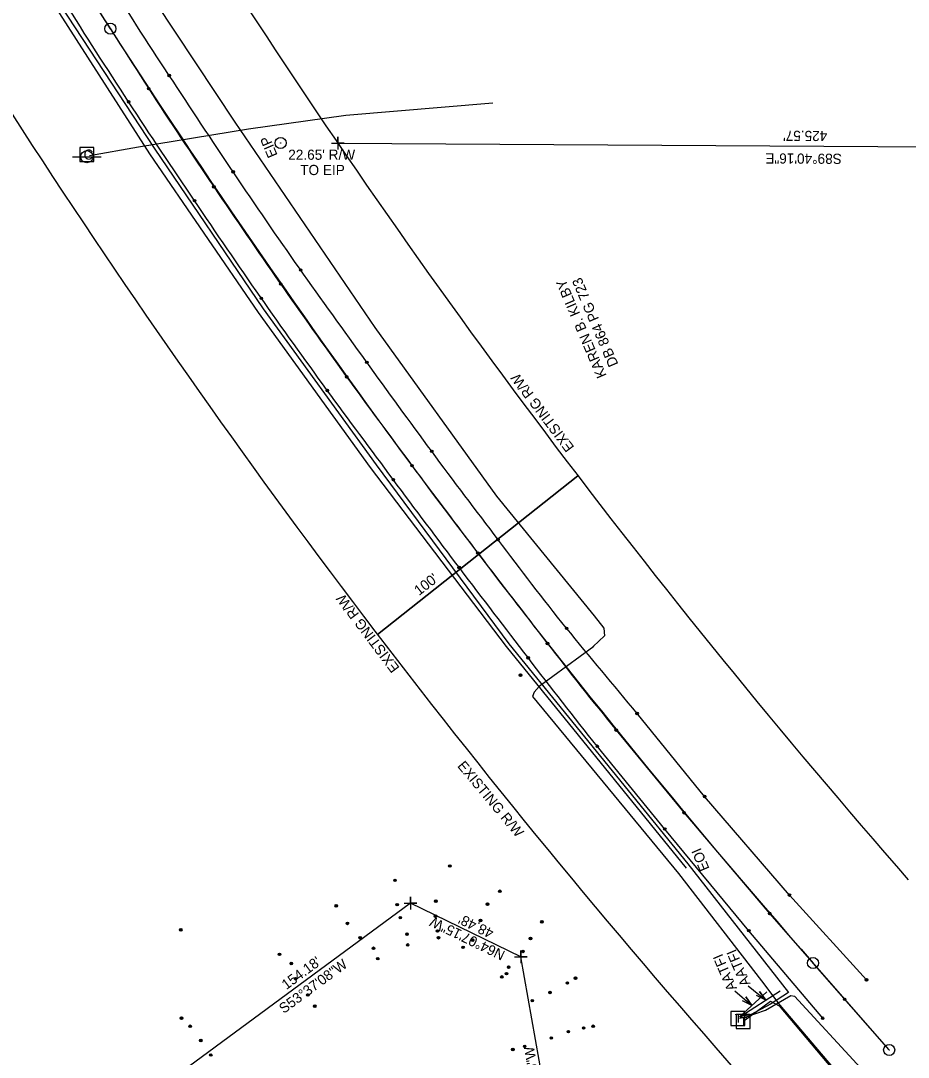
# Model space of a CAD drawing. Extents: x 1550153 to 1552579, y 809637 to 812160.
# Drawn here: x 1552025.7 to 1552376.2, y 809876 to 810285.6 of the extents above; entities that cross this region are included whole.
import ezdxf

# ---------------------------------------------------------------- set-up
doc = ezdxf.new("R2010")
doc.units = 0
for name, color, linetype in [('Default', 7, 'Continuous'), ('E_NCDOT_Horizontal_Alignment', 7, 'Continuous'), ('E_NCDOT_Horizontal_Alignment_Curve', 7, 'Continuous'), ('E_NCDOT_Horizontal_Alignment_Tick_Label', 7, 'Continuous'), ('Exist DTM Crownline', 7, 'Continuous'), ('Exist Other Culture Area Outline Text', 7, 'Continuous'), ('Exist Property Corner CELL', 7, 'Continuous'), ('Exist Property Iron Pin CELL', 7, 'Continuous'), ('Exist Property Iron Pin Text', 7, 'Continuous'), ('Exist Property Line', 7, 'Continuous'), ('Exist Property Line Text', 7, 'Continuous'), ('Exist Property Text', 7, 'Continuous'), ('Exist Right of Way Line', 7, 'Continuous'), ('Exist Right of Way Line Leader', 7, 'Continuous'), ('Exist Right of Way Line Text', 7, 'Continuous'), ('Exist Roads EOP', 7, 'Continuous'), ('Exist Utilities Other Text', 7, 'Continuous'), ('Exist Utilities Other Unknown UG SUE LOS B', 7, 'Continuous'), ('Exist Utilities Telephone Pedestal CELL', 7, 'Continuous'), ('Exist Utilities Telephone Pole CELL', 7, 'Continuous'), ('Exist Utilities Telephone Text', 7, 'Continuous'), ('Exist Utilities Telephone UG Cable SUE LOS B', 7, 'Continuous'), ('Exist Utilities Telephone UG FO SUE LOS B', 7, 'Continuous'), ('Exist Utilities TV Pedestal CELL', 7, 'Continuous'), ('Exist Utilities TV UG Cable SUE LOS B', 7, 'Continuous')]:
    doc.layers.add(name, color=color, linetype=linetype)

# ---------------------------------------------------------------- blocks, each defined once
blk = doc.blocks.new('SurveyPointCell')
at = {"layer": 'Default'}
for p, q in [((-0.5, 0), (0.5, 0)), ((0, -0.5), (0, 0.5))]:
    blk.add_line(p, q, dxfattribs=at)
blk.add_circle((0, 0), 0.5, dxfattribs=at)

msp = doc.modelspace()

# ---------------------------------------------------------------- linework, layer by layer
at = {"layer": 'Default'}
msp.add_arc((1554670.98, 811955.32), 3100, 212.65834, 221.20382, dxfattribs=at)
msp.add_arc((1554670.98, 811955.32), 3100, 212.65834, 221.20382, dxfattribs=at)
msp.add_arc((1554670.98, 811955.32), 3100, 212.65834, 221.20382, dxfattribs=at)
at = {"layer": 'E_NCDOT_Horizontal_Alignment'}
for p, q in [((1552061.08, 810282.48), (1552050.68, 810298.74)), ((1552368.71, 809878.88), (1552338.63, 809913.23))]:
    msp.add_line(p, q, dxfattribs=at)
for centre, radius in [((1552061.08, 810282.48), 2.2), ((1552061.08, 810282.48), 0.0707), ((1552338.63, 809913.23), 2.2), ((1552338.63, 809913.23), 0.0707), ((1552368.71, 809878.88), 2.2), ((1552368.71, 809878.88), 0.0707)]:
    msp.add_circle(centre, radius, dxfattribs=at)
at = {"layer": 'E_NCDOT_Horizontal_Alignment_Curve'}
msp.add_arc((1554670.98, 811955.32), 3100, 212.65834, 221.20382, dxfattribs=at)
msp.add_arc((1554670.98, 811955.32), 3100, 212.65834, 221.20382, dxfattribs=at)
at = {"layer": 'E_NCDOT_Horizontal_Alignment_Tick_Label'}
msp.add_arc((1554670.98, 811955.32), 3100, 212.65834, 221.20382, dxfattribs=at)
at = {"layer": 'Exist DTM Crownline'}
for p, q in [((1552260.85, 810005.29), (1552287.67, 809972.63)), ((1552260.85, 810005.29), (1552287.67, 809972.63)), ((1552287.67, 809972.63), (1552321.49, 809932.79)), ((1552287.67, 809972.63), (1552321.49, 809932.79)), ((1552321.49, 809932.79), (1552351.14, 809898.88)), ((1552321.49, 809932.79), (1552351.14, 809898.88))]:
    msp.add_line(p, q, dxfattribs=at)
msp.add_open_spline([(1551879.82, 810614.22), (1551884.05, 810605.39), (1551895.17, 810581.82), (1551913.83, 810543.92), (1551935.88, 810500.73), (1551958.31, 810458.41), (1551980.95, 810417.48), (1552003.45, 810377.54), (1552026.55, 810337.94), (1552050.88, 810298.4), (1552075.94, 810258.8), (1552101.84, 810219.91), (1552127.91, 810181.93), (1552154.01, 810145.21), (1552180.08, 810109.84), (1552206.53, 810074.71), (1552233.39, 810039.85), (1552251.62, 810016.53), (1552260.85, 810005.29)], degree=3, dxfattribs=at)
msp.add_open_spline([(1551879.82, 810614.22), (1551884.05, 810605.39), (1551895.17, 810581.82), (1551913.83, 810543.92), (1551935.88, 810500.73), (1551958.31, 810458.41), (1551980.95, 810417.48), (1552003.45, 810377.54), (1552026.55, 810337.94), (1552050.88, 810298.4), (1552075.94, 810258.8), (1552101.84, 810219.91), (1552127.91, 810181.93), (1552154.01, 810145.21), (1552180.08, 810109.84), (1552206.53, 810074.71), (1552233.39, 810039.85), (1552251.62, 810016.53), (1552260.85, 810005.29)], degree=3, dxfattribs=at)
at = {"layer": 'Exist Other Culture Area Outline Text'}
msp.add_line((1552368.71, 809878.88), (1552351.02, 809899.07), dxfattribs=at)
at = {"layer": 'Exist Property Corner CELL'}
for p, q in [((1552150.95, 810237.19), (1552150.95, 810237.19)), ((1552179.62, 809936.85), (1552179.62, 809936.85)), ((1552223.24, 809915.69), (1552223.24, 809915.69))]:
    msp.add_line(p, q, dxfattribs=at)
for points in [[(1552148.45, 810237.19), (1552153.45, 810237.19), (1552150.95, 810237.19), (1552150.95, 810239.69), (1552150.95, 810234.69)], [(1552177.12, 809936.85), (1552182.12, 809936.85), (1552179.62, 809936.85), (1552179.62, 809939.35), (1552179.62, 809934.35)], [(1552220.74, 809915.69), (1552225.74, 809915.69), (1552223.24, 809915.69), (1552223.24, 809918.19), (1552223.24, 809913.19)]]:
    msp.add_lwpolyline(points, dxfattribs=at)
at = {"layer": 'Exist Property Iron Pin CELL'}
for radius in [2.2, 2.2, 0.0707, 0.0707]:
    msp.add_circle((1552128.3, 810237.32), radius, dxfattribs=at)
at = {"layer": 'Exist Property Line'}
for p, q in [((1552150.95, 810237.19), (1552576.51, 810234.75)), ((1552179.62, 809936.85), (1552055.49, 809845.39)), ((1552223.24, 809915.69), (1552179.62, 809936.85)), ((1552240.21, 809820.15), (1552223.24, 809915.69))]:
    msp.add_line(p, q, dxfattribs=at)
at = {"layer": 'Exist Right of Way Line'}
msp.add_line((1552300.27, 809879.66), (1552330.35, 809845.3), dxfattribs=at)
for centre, radius, start in [((1554670.98, 811955.32), 3050, 212.65885), ((1554670.24, 811954.69), 3150, 212.65834)]:
    msp.add_arc(centre, radius, start, 221.20382, dxfattribs=at)
at = {"layer": 'Exist Right of Way Line Leader'}
for p, q in [((1552166.59, 810043.11), (1552245.77, 810105.76)), ((1552245.77, 810105.76), (1552166.59, 810043.11))]:
    msp.add_line(p, q, dxfattribs=at)
at = {"layer": 'Exist Roads EOP'}
for p, q in [((1552295.82, 809979.06), (1552269.13, 810011.86)), ((1552295.82, 809979.06), (1552269.13, 810011.86)), ((1552280.06, 809966.19), (1552253.42, 809998.9)), ((1552280.06, 809966.19), (1552253.42, 809998.9)), ((1552329.3, 809940.08), (1552295.82, 809979.06)), ((1552329.3, 809940.08), (1552295.82, 809979.06)), ((1552313.28, 809926.01), (1552280.06, 809966.19)), ((1552313.28, 809926.01), (1552280.06, 809966.19)), ((1552359.73, 809906.61), (1552329.3, 809940.08)), ((1552359.73, 809906.61), (1552329.3, 809940.08)), ((1552342.44, 809891.42), (1552313.28, 809926.01)), ((1552342.44, 809891.42), (1552313.28, 809926.01))]:
    msp.add_line(p, q, dxfattribs=at)
for points in [[(1552269.13, 810011.86), (1552259.93, 810023.16), (1552240.78, 810045.4), (1552214.35, 810080.42), (1552187.88, 810115.33), (1552162.14, 810151.01), (1552135.65, 810187.58), (1552109.73, 810225.45), (1552084.16, 810264.07), (1552058.92, 810303.06), (1552035.07, 810342.61), (1552011.65, 810381.94), (1551989.05, 810421.66), (1551966.76, 810462.54), (1551944.71, 810504.82), (1551922.39, 810547.43), (1551904.23, 810585.99), (1551891.95, 810609.53), (1551888.02, 810619.12)], [(1552269.13, 810011.86), (1552259.93, 810023.16), (1552240.78, 810045.4), (1552214.35, 810080.42), (1552187.88, 810115.33), (1552162.14, 810151.01), (1552135.65, 810187.58), (1552109.73, 810225.45), (1552084.16, 810264.07), (1552058.92, 810303.06), (1552035.07, 810342.61), (1552011.65, 810381.94), (1551989.05, 810421.66), (1551966.76, 810462.54), (1551944.71, 810504.82), (1551922.39, 810547.43), (1551904.23, 810585.99), (1551891.95, 810609.53), (1551888.02, 810619.12)], [(1552253.42, 809998.9), (1552244.08, 810010.36), (1552226.02, 810034.01), (1552199.09, 810069.05), (1552172.75, 810104.35), (1552146.51, 810139.68), (1552120.18, 810176.35), (1552094.25, 810214.54), (1552068.09, 810253.47), (1552042.85, 810293.18), (1552018.16, 810332.74), (1551995.33, 810372.57), (1551972.36, 810412.53), (1551950.07, 810453.8), (1551927.46, 810496.24), (1551905.63, 810539.48), (1551886.95, 810576.34), (1551876.35, 810599.18), (1551872.14, 810607.04)], [(1552253.42, 809998.9), (1552244.08, 810010.36), (1552226.02, 810034.01), (1552199.09, 810069.05), (1552172.75, 810104.35), (1552146.51, 810139.68), (1552120.18, 810176.35), (1552094.25, 810214.54), (1552068.09, 810253.47), (1552042.85, 810293.18), (1552018.16, 810332.74), (1551995.33, 810372.57), (1551972.36, 810412.53), (1551950.07, 810453.8), (1551927.46, 810496.24), (1551905.63, 810539.48), (1551886.95, 810576.34), (1551876.35, 810599.18), (1551872.14, 810607.04)]]:
    msp.add_open_spline(points, degree=3, dxfattribs=at)
at = {"layer": 'Exist Utilities Other Unknown UG SUE LOS B'}
msp.add_lwpolyline([(1551998.29, 810358.65), (1552027.49, 810309.53), (1552076.51, 810232.97), (1552119.42, 810170.33), (1552163.65, 810109.03), (1552217.37, 810038.38), (1552288.47, 809950.78)], dxfattribs=at)
at = {"layer": 'Exist Utilities Telephone Pedestal CELL'}
for p, q in [((1552308.86, 809891.37), (1552308.86, 809891.37)), ((1552310.97, 809890.17), (1552310.97, 809890.17))]:
    msp.add_line(p, q, dxfattribs=at)
for points in [[(1552306.13, 809888.54), (1552311.73, 809888.54), (1552311.73, 809894.14), (1552306.13, 809894.14), (1552306.13, 809888.54)], [(1552308.24, 809887.34), (1552313.84, 809887.34), (1552313.84, 809892.93), (1552308.24, 809892.93), (1552308.24, 809887.34)]]:
    msp.add_lwpolyline(points, dxfattribs=at)
at = {"layer": 'Exist Utilities Telephone Pole CELL'}
for p, q in [((1552046.12, 810231.89), (1552057.46, 810231.89)), ((1552051.8, 810231.89), (1552051.8, 810231.89))]:
    msp.add_line(p, q, dxfattribs=at)
msp.add_circle((1552051.8, 810231.89), 2.41, dxfattribs=at)
at = {"layer": 'Exist Utilities Telephone Text'}
for points in [[(1552313.06, 809904.27), (1552320, 809898.6), (1552317.53, 809901.92), (1552320, 809898.6), (1552316.25, 809900.36)], [(1552307.68, 809902.3), (1552314.5, 809896.48), (1552312.1, 809899.85), (1552314.5, 809896.48), (1552310.79, 809898.32)]]:
    msp.add_lwpolyline(points, dxfattribs=at)
at = {"layer": 'Exist Utilities Telephone UG Cable SUE LOS B'}
for points in [[(1551973.26, 810338.34), (1551996.17, 810347.86), (1551999.41, 810348.48), (1552003.26, 810346.04), (1552024.7, 810309.34), (1552030.08, 810308.97), (1552078.4, 810235.23), (1552121.38, 810171.79), (1552166.12, 810110.11), (1552218.44, 810039.34), (1552289.22, 809952.46), (1552328.94, 809901.56), (1552321.82, 809896.99), (1552314.14, 809892.89), (1552309.87, 809891.97)], [(1552309.55, 809891.47), (1552312.19, 809891.91), (1552319.91, 809894.61), (1552329.89, 809900.42), (1552331.29, 809900.19), (1552357.54, 809871.63), (1552412.1, 809813.52), (1552394.77, 809791.06), (1552373.8, 809767.63)], [(1552309.62, 809892), (1552320.35, 809901.83)], [(1552309.74, 809892), (1552325.61, 809902.19)]]:
    msp.add_lwpolyline(points, dxfattribs=at)
at = {"layer": 'Exist Utilities Telephone UG FO SUE LOS B'}
for points in [[(1552044.44, 810374.04), (1552034.64, 810367.89), (1552033.1, 810366.21), (1552033.06, 810365.23), (1552055.35, 810328.54), (1552110.28, 810245.54), (1552165.47, 810164.33), (1552213.57, 810097.71), (1552252.14, 810050.46), (1552256.04, 810045.54), (1552256.3, 810042.48), (1552251.81, 810038.38)], [(1552252.06, 810038.28), (1552230.41, 810022.46), (1552228.43, 810020.33), (1552227.78, 810018.51), (1552285.44, 809948.57), (1552318.22, 809906.19), (1552325.57, 809896.61), (1552350.79, 809866.81), (1552393.46, 809818.55), (1552396.72, 809805.6), (1552391.99, 809793.83), (1552373.15, 809768.18)], [(1552311.27, 809890.39), (1552321.89, 809898.14), (1552325.31, 809896.34), (1552350.52, 809866.22), (1552392.74, 809818.07), (1552396.32, 809805.59), (1552391.17, 809793.53), (1552372.89, 809768.53)]]:
    msp.add_lwpolyline(points, dxfattribs=at)
at = {"layer": 'Exist Utilities TV Pedestal CELL'}
msp.add_line((1552051.77, 810232.73), (1552051.77, 810232.73), dxfattribs=at)
msp.add_lwpolyline([(1552049, 810229.96), (1552054.55, 810229.96), (1552054.55, 810235.51), (1552049, 810235.51), (1552049, 810229.96)], dxfattribs=at)
at = {"layer": 'Exist Utilities TV UG Cable SUE LOS B'}
msp.add_lwpolyline([(1552052.75, 810232.34), (1552072.2, 810235.77), (1552115.56, 810242.96), (1552154.04, 810248.3), (1552212.2, 810253.17)], dxfattribs=at)

# ---------------------------------------------------------------- block references
at = {"layer": 'Default'}
for p in [(1552084.32, 810263.97), (1552084.32, 810263.97), (1552076.17, 810258.78), (1552076.17, 810258.78), (1552068.28, 810253.55), (1552068.28, 810253.55), (1552109.57, 810225.89), (1552109.57, 810225.89), (1552101.92, 810219.98), (1552101.92, 810219.98), (1552094.32, 810214.5), (1552094.32, 810214.5), (1552136.23, 810187.11), (1552136.23, 810187.11), (1552128.32, 810181.56), (1552128.32, 810181.56), (1552120.71, 810175.94), (1552120.71, 810175.94), (1552162.39, 810150.64), (1552162.39, 810150.64), (1552154.39, 810144.9), (1552154.39, 810144.9), (1552146.79, 810139.5), (1552146.79, 810139.5), (1552188.02, 810115.43), (1552188.02, 810115.43), (1552180.2, 810109.81), (1552180.2, 810109.81), (1552172.86, 810104.22), (1552172.86, 810104.22), (1552214.18, 810080.63), (1552214.18, 810080.63), (1552206.22, 810075.25), (1552206.22, 810075.25), (1552198.86, 810069.53), (1552198.86, 810069.53), (1552241.29, 810045.52), (1552241.29, 810045.52), (1552233.73, 810039.5), (1552233.73, 810039.5), (1552226.12, 810033.84), (1552226.12, 810033.84), (1552223.06, 810026.98), (1552223.06, 810026.98), (1552269.13, 810011.86), (1552269.13, 810011.86), (1552260.85, 810005.29), (1552260.85, 810005.29), (1552253.42, 809998.9), (1552253.42, 809998.9), (1552295.82, 809979.06), (1552295.82, 809979.06), (1552287.67, 809972.63), (1552287.67, 809972.63), (1552280.06, 809966.19), (1552280.06, 809966.19), (1552195.17, 809951.6), (1552195.17, 809951.6), (1552173.48, 809945.94), (1552173.48, 809945.94), (1552214.92, 809941.61), (1552214.92, 809941.61), (1552329.3, 809940.08), (1552329.3, 809940.08), (1552150.28, 809935.83), (1552150.28, 809935.83), (1552174.36, 809936.3), (1552174.36, 809936.3), (1552189.61, 809937.68), (1552189.61, 809937.68), (1552210.02, 809936.48), (1552210.02, 809936.48), (1552175.6, 809931.14), (1552175.6, 809931.14), (1552189.5, 809931.74), (1552189.5, 809931.74), (1552321.49, 809932.79), (1552321.49, 809932.79), (1552154.7, 809928.89), (1552154.7, 809928.89), (1552207.25, 809930.02), (1552207.25, 809930.02), (1552231.53, 809929.5), (1552231.53, 809929.5), (1552088.86, 809926.35), (1552088.86, 809926.35), (1552159.72, 809923.22), (1552159.72, 809923.22), (1552178.25, 809924.63), (1552178.25, 809924.63), (1552190.26, 809925.9), (1552190.26, 809925.9), (1552190.66, 809923.22), (1552190.66, 809923.22), (1552227.04, 809922.95), (1552227.04, 809922.95), (1552313.28, 809926.01), (1552313.28, 809926.01), (1552165.01, 809919.08), (1552165.01, 809919.08), (1552178.52, 809920.39), (1552178.52, 809920.39), (1552200.39, 809919.42), (1552200.39, 809919.42), (1552204.19, 809922.29), (1552204.19, 809922.29), (1552127.85, 809916.66), (1552127.85, 809916.66), (1552166.68, 809914.97), (1552166.68, 809914.97), (1552224.06, 809917.82), (1552224.06, 809917.82), (1552132.52, 809913.06), (1552132.52, 809913.06), (1552218.37, 809911.62), (1552218.37, 809911.62), (1552134.22, 809907.02), (1552134.22, 809907.02), (1552215.7, 809907.75), (1552215.7, 809907.75), (1552217.52, 809909.01), (1552217.52, 809909.01), (1552244.8, 809907.27), (1552244.8, 809907.27), (1552359.73, 809906.61), (1552359.73, 809906.61), (1552241.58, 809905.36), (1552241.58, 809905.36), (1552139.07, 809900.6), (1552139.07, 809900.6), (1552227.74, 809898.36), (1552227.74, 809898.36), (1552234.74, 809901.57), (1552234.74, 809901.57), (1552351.14, 809898.88), (1552351.14, 809898.88), (1552141.79, 809896.18), (1552141.79, 809896.18), (1552089.16, 809891.44), (1552089.16, 809891.44), (1552342.44, 809891.42), (1552342.44, 809891.42), (1552092.58, 809888.26), (1552092.58, 809888.26), (1552241.98, 809886.09), (1552241.98, 809886.09), (1552248, 809887.58), (1552248, 809887.58), (1552251.76, 809888.26), (1552251.76, 809888.26), (1552096.76, 809882.61), (1552096.76, 809882.61), (1552235.23, 809883.62), (1552235.23, 809883.62), (1552220.03, 809879.07), (1552220.03, 809879.07), (1552224.73, 809880.33), (1552224.73, 809880.33), (1552100.71, 809876.89), (1552100.71, 809876.89)]:
    msp.add_blockref('SurveyPointCell', p, dxfattribs=at)

# ---------------------------------------------------------------- texts
at = {"layer": 'Exist Property Iron Pin Text'}
msp.add_text('EIP', height=4.02, rotation=113.1736, dxfattribs=at).set_placement((1552127.19, 810232.52))
at = {"layer": 'Exist Property Line Text'}
for s, rotation, p in [("425.57'", 179.6712, (1552344.27, 810242.07)), ('S89°40\'16"E', 179.6712, (1552350, 810233.05)), ("48.48'", 154.1208, (1552212.89, 809926.37)), ('N64°07\'15"W', 154.1208, (1552217.32, 809917.74)), ('S53°37\'08"W', 36.3811, (1552129.56, 809893.09)), ("154.18'", 36.3811, (1552130.58, 809902.52)), ('N10°04\'26"W', 100.0739, (1552233.93, 809849.02))]:
    msp.add_text(s, height=4.02, rotation=rotation, dxfattribs=at).set_placement(p)
for s, p in [("22.65' R/W", (1552131.32, 810230.66)), ('TO EIP', (1552136.05, 810224.63))]:
    msp.add_text(s, height=4.02, dxfattribs=at).set_placement(p)
at = {"layer": 'Exist Property Text'}
for s, p in [('KAREN B. KILBY', (1552257.16, 810145.4)), ('DB 864 PG 723', (1552261.8, 810149.88))]:
    msp.add_text(s, height=4.02, rotation=113.1736, dxfattribs=at).set_placement(p)
at = {"layer": 'Exist Right of Way Line Text'}
for s, rotation, p in [('EXISTING R/W', 127.0245, (1552244.47, 810117.11)), ("100'", 37.7703, (1552183.01, 810058.27)), ('EXISTING R/W', 126.9869, (1552175.49, 810029.88)), ('EXISTING R/W', 309.7837, (1552197.9, 809991.02))]:
    msp.add_text(s, height=4.02, rotation=rotation, dxfattribs=at).set_placement(p)
at = {"layer": 'Exist Utilities Other Text'}
msp.add_text('EOI', height=4.02, rotation=113.1736, dxfattribs=at).set_placement((1552297.8, 809950.56))
at = {"layer": 'Exist Utilities Telephone Pedestal CELL'}
for p in [(1552307.73, 809889.66), (1552309.84, 809888.45)]:
    msp.add_text('T', height=3.42, dxfattribs=at).set_placement(p)
at = {"layer": 'Exist Utilities Telephone Text'}
for p in [(1552308.62, 809903.24), (1552314, 809905.06)]:
    msp.add_text('AATFI', height=4.02, rotation=113.1736, dxfattribs=at).set_placement(p)
at = {"layer": 'Exist Utilities TV Pedestal CELL'}
msp.add_text('C', height=4, dxfattribs=at).set_placement((1552050.46, 810230.73))

doc.saveas('drawing.dxf')
